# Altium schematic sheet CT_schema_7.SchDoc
size 371 x 336 mm
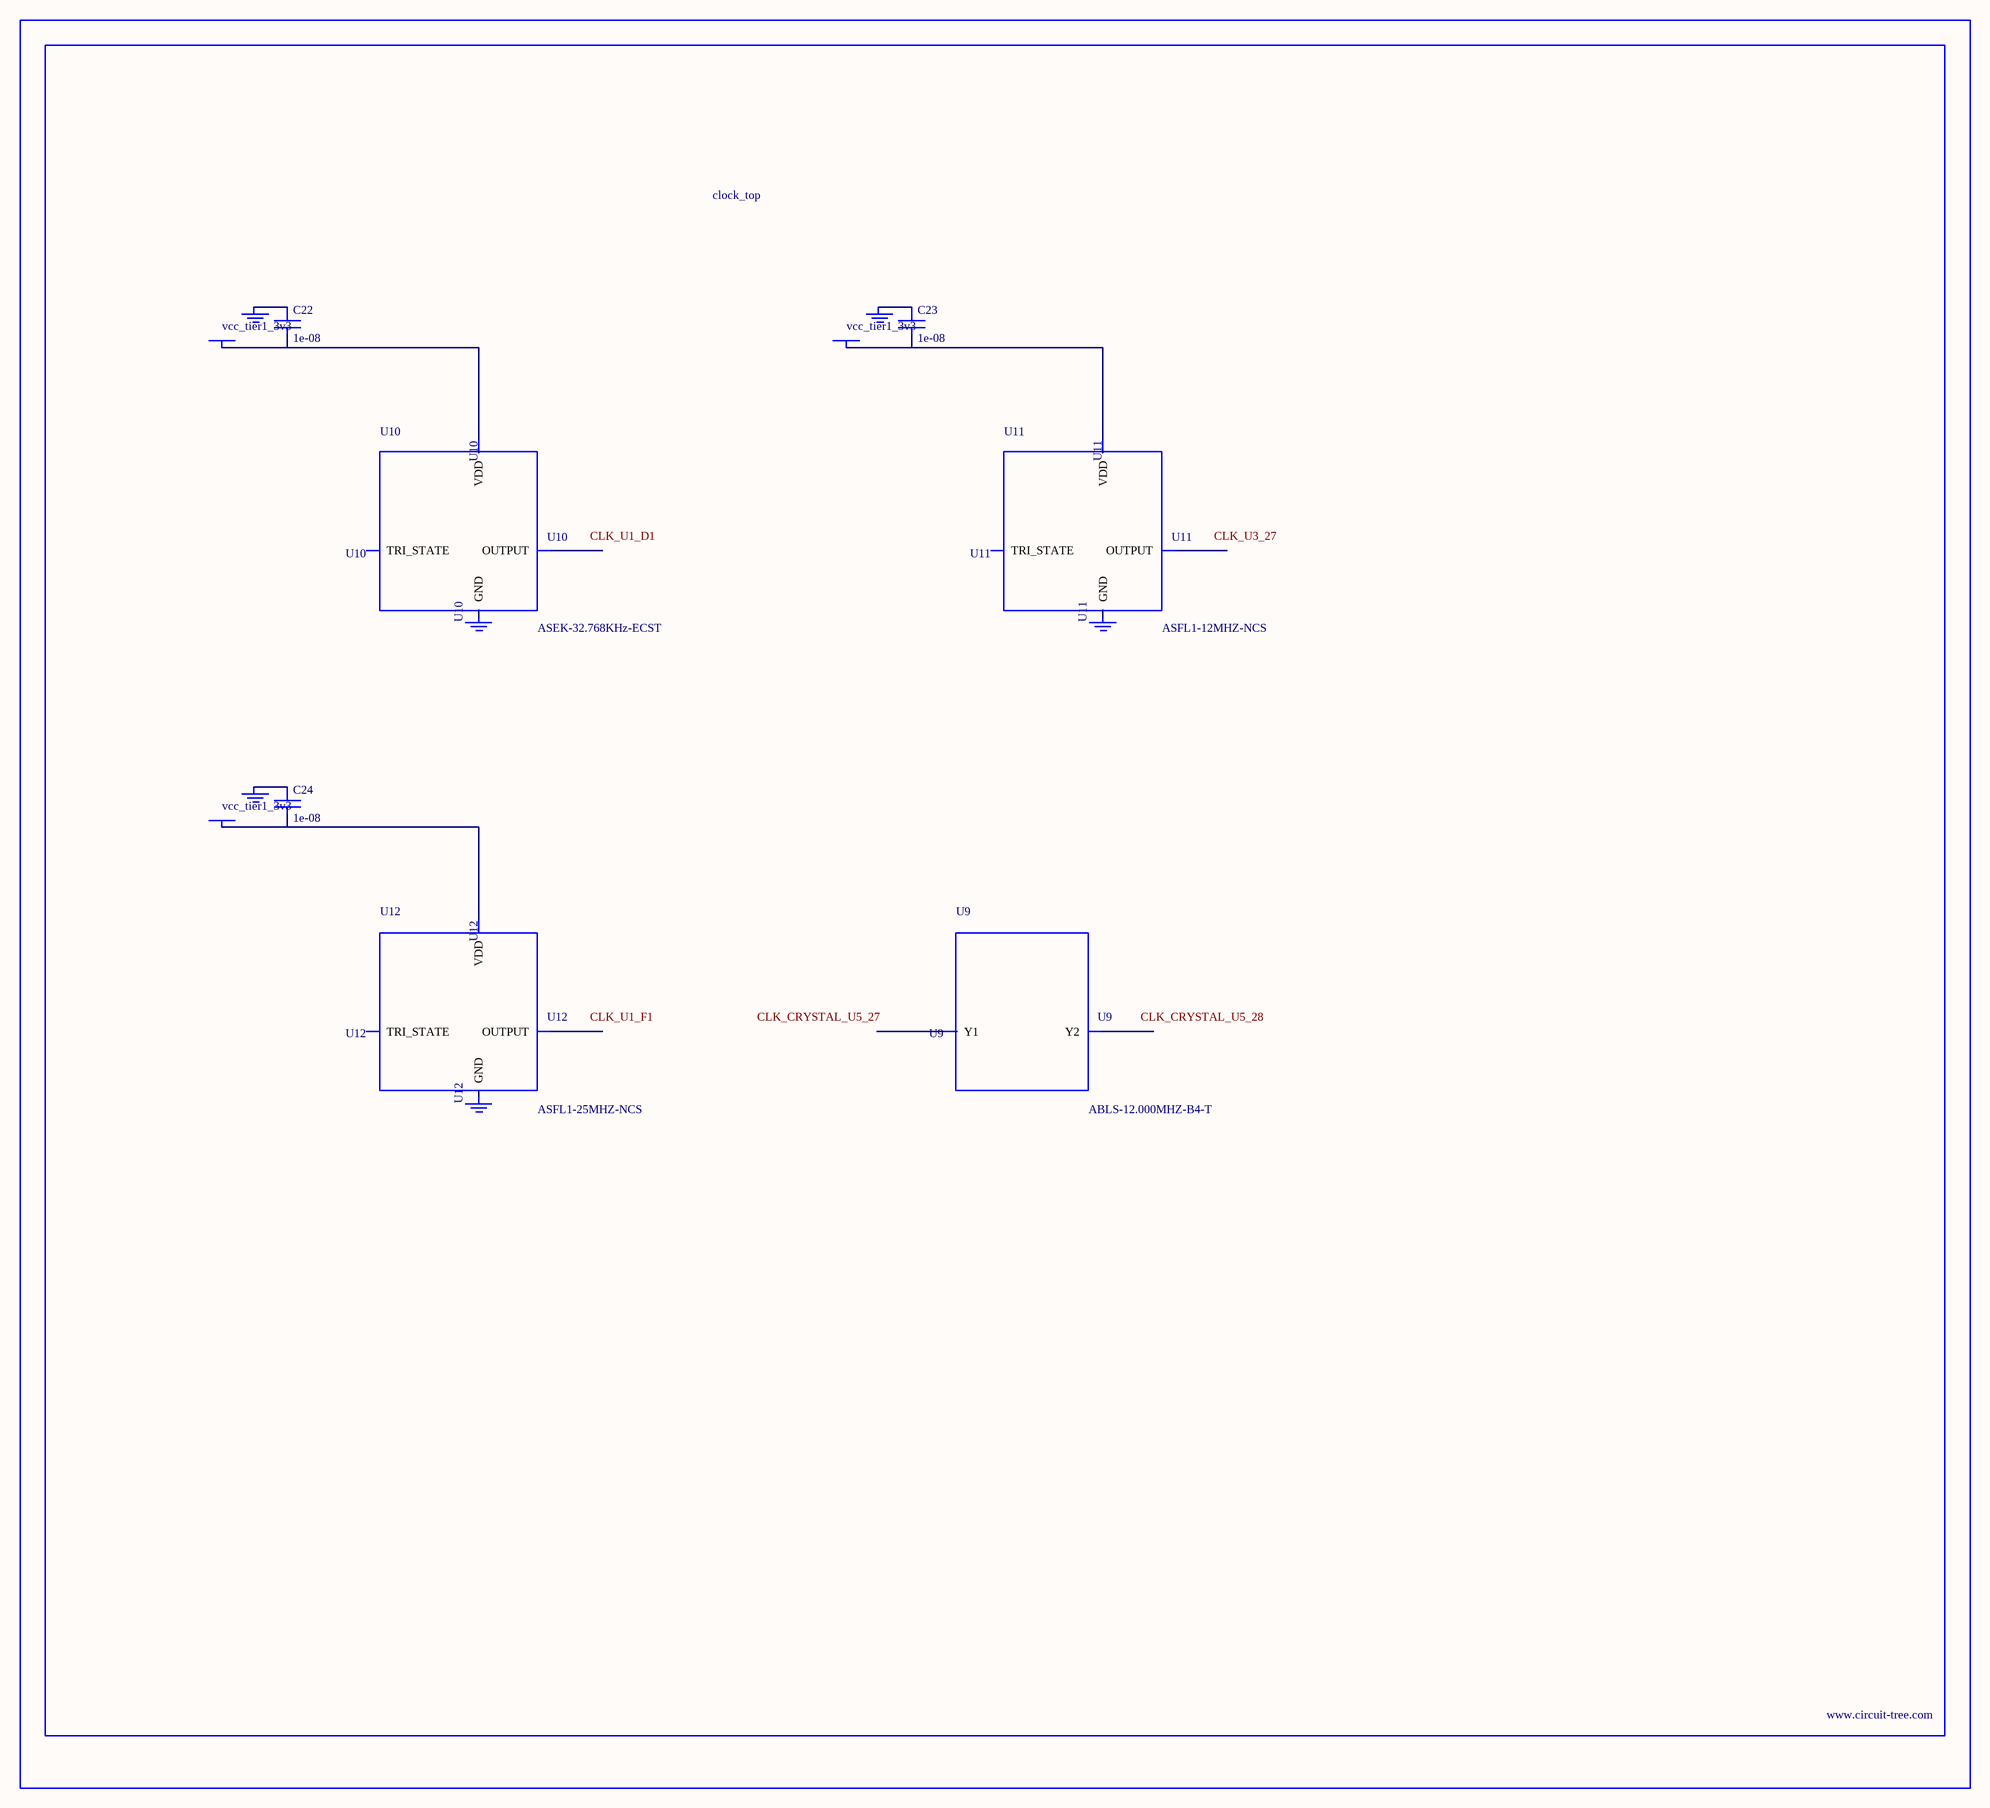
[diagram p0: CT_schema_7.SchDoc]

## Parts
BORDER6  (no value)
C22  1e-08  [C0402]
C23  1e-08  [C0402]
C24  1e-08  [C0402]
GND_INSTANCE_6_0  (no value)
GND_INSTANCE_6_1  (no value)
GND_INSTANCE_6_2  (no value)
GND_INSTANCE_6_3  (no value)
GND_INSTANCE_6_4  (no value)
GND_INSTANCE_6_5  (no value)
POWER_INSTANCE_6_0  vcc_tier1_3v3
POWER_INSTANCE_6_1  vcc_tier1_3v3
POWER_INSTANCE_6_2  vcc_tier1_3v3
U9  ABLS-12.000MHZ-B4-T  [ABLS-12.000MHZ-B4-T]
U10  ASEK-32.768KHz-ECST  [ASEK]
U11  ASFL1-12MHZ-NCS  [ASFL1]
U12  ASFL1-25MHZ-NCS  [ASFL1]

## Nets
NetC22_1: C22.1 GND_INSTANCE_6_0.0(GND)
NetC22_2: C22.2 POWER_INSTANCE_6_0.0(PWR) U10.4(VDD)
NetC23_1: C23.1 GND_INSTANCE_6_2.0(GND)
NetC23_2: C23.2 POWER_INSTANCE_6_1.0(PWR) U11.4(VDD)
NetC24_1: C24.1 GND_INSTANCE_6_4.0(GND)
NetC24_2: C24.2 POWER_INSTANCE_6_2.0(PWR) U12.4(VDD)

Not connected (* = marked no-connect by the designer): GND_INSTANCE_6_1 0(GND); GND_INSTANCE_6_3 0(GND); GND_INSTANCE_6_5 0(GND); U9 1(Y1) 2(Y2); U10 1(TRI_STATE) 2(GND) 3(OUTPUT); U11 1(TRI_STATE) 2(GND) 3(OUTPUT); U12 1(TRI_STATE) 2(GND) 3(OUTPUT)

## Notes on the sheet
- Labels drawn without touching a wire or pin: CLK_CRYSTAL_U5_27, CLK_CRYSTAL_U5_28, CLK_U1_D1, CLK_U1_F1, CLK_U3_27

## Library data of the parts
BORDER6 = BORDER_PAGE6
C22-C24 = C0402C103K3RAC
GND_INSTANCE_6_0-GND_INSTANCE_6_5 = GND
POWER_INSTANCE_6_0-POWER_INSTANCE_6_2 = PWR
